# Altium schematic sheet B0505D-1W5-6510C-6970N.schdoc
size 277 x 190 mm; Device: default297x210; Symbol: default297x210; Name: default297x210; Date: 2026.03.13; Rev: V1.0; Size: "A4"; Id: /; File: B0505D-1W5-6510C-6970N; Sheet: /
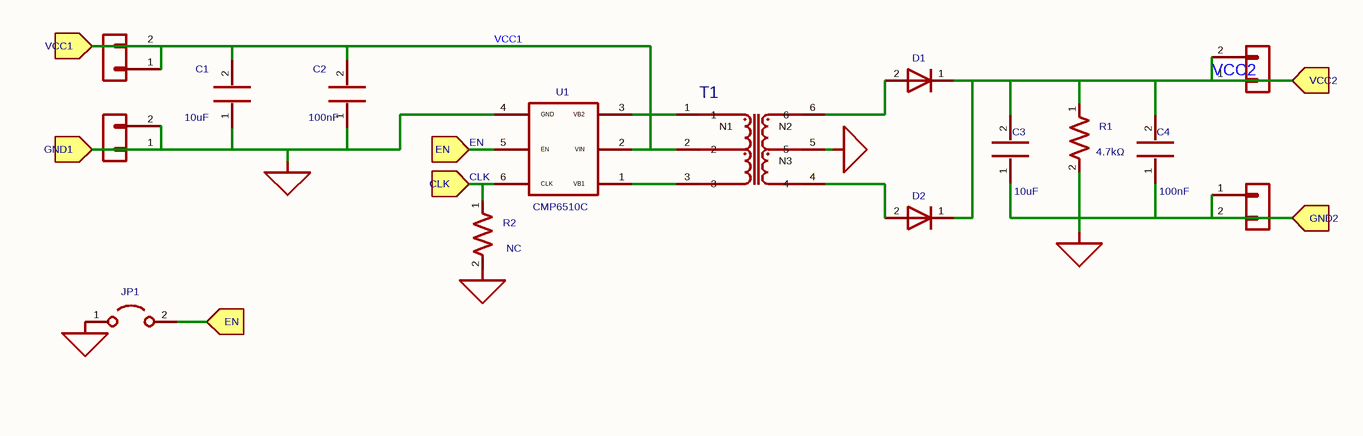
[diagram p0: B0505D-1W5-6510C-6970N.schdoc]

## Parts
C1  10uF  [MYLibrary:C0603]
C2  100nF  [MYLibrary:C0603]
C3  10uF  [MYLibrary:C0603]
C4  100nF  [MYLibrary:C0603]
D1  B5819W  [MYLibrary:SOD-123-323]  (value not drawn)
D2  B5819W  [MYLibrary:SOD-123-323]  (value not drawn)
J2  HX PZ2.54-1x2P ZZ  [Connector_PinHeader_2.54mm:PinHeader_1x02_P2.54mm_Vertical]  (value not drawn)
J3  HX PZ2.54-1x2P ZZ  [Connector_PinHeader_2.54mm:PinHeader_1x02_P2.54mm_Vertical]  (value not drawn)
J4  HX PZ2.54-1x2P ZZ  [Connector_PinHeader_2.54mm:PinHeader_1x02_P2.54mm_Vertical]  (value not drawn)
J5  Connector_Generic_Conn_01x02  [Connector_PinHeader_2.54mm:PinHeader_1x02_P2.54mm_Vertical]  (value not drawn)
JP1  Jumper_Jumper_2_Open  [Connector_PinHeader_2.54mm:PinHeader_1x02_P2.54mm_Vertical]  (value not drawn)
R1  4.7kΩ  [MYLibrary:R0603]
R2  value NC  [MYLibrary:R0603]  (hidden comment: My_Library_R)
T1  (no value)  [CMT6970N]
U1  value CMP6510C  [MYLibrary:SOT23-6]  (hidden comment: MYLibrary _CMP6510C)

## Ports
CLK (in), EN (in), GND1 (in), GND2 (in), VCC1 (in), VCC2 (in)

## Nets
GND1: C1.1 C2.1 J3.1(Pin_1) J3.2(Pin_2) JP1.1(A) R2.2 U1.4(GND) ; port GND1
GND2: C3.1 C4.1 J5.1(Pin_1) J5.2(Pin_2) R1.2 T1.5 ; port GND2
CLK: R2.1 U1.6(CLK) ; port CLK
EN: JP1.2(B) U1.5(EN) ; port EN
VCC1: C1.2 C2.2 J2.1(Pin_1) J2.2(Pin_2) T1.2 U1.2(VIN) ; port VCC1
VCC2: C3.2 C4.2 D1.1(K) D2.1(K) J4.1(Pin_1) J4.2(Pin_2) R1.1 ; port VCC2
NetD1_2: D1.2(A) T1.6
NetD2_2: D2.2(A) T1.4
NetT1_1: T1.1 U1.3(VB2)
NetT1_3: T1.3 U1.1(VB1)

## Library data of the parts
C1 = 0603X106K100NT: 容值:10uF;精度:±10%;额定电压:10V;温度系数:X5R;; Manufacturer: FH(风华); Symbol: My_Library_C; Add into BOM: yes; 3D Model: ac125912035d415993ca9572d50418b1; 3D Model Transform: 62.992,31.496,0,0,0,0,0,0,0; Tolerance: ±10%; Voltage Rating: 10V; Temperature Coefficient: X5R; ki_keywords: cap capacitor; ki_fp_filters: C_*; UniqueId: 5fb4f22ffcb6a001; ModelName: C0603_L1.6-W0.8-H0.8
C2 = CC0603KRX7R9BB104: 容值:100nF;精度:±10%;额定电压:50V;温度系数:X7R;; Manufacturer: YAGEO(国巨); Symbol: My_Library_C; Add into BOM: yes; 3D Model: ac125912035d415993ca9572d50418b1; 3D Model Transform: 62.992,31.496,0,0,0,0,0,0,0; Tolerance: ±10%; Voltage Rating: 50V; Temperature Coefficient: X7R; ki_keywords: cap capacitor; ki_fp_filters: C_*; UniqueId: 21d50210554cb61f; ModelName: C0603_L1.6-W0.8-H0.8
C3 = 0603X106K100NT: 容值:10uF;精度:±10%;额定电压:10V;温度系数:X5R;; Manufacturer: FH(风华); Symbol: My_Library_C; Add into BOM: yes; 3D Model: ac125912035d415993ca9572d50418b1; 3D Model Transform: 62.992,31.496,0,0,0,0,0,0,0; Tolerance: ±10%; Voltage Rating: 10V; Temperature Coefficient: X5R; ki_keywords: cap capacitor; ki_fp_filters: C_*; ModelName: C0603_L1.6-W0.8-H0.8
C4 = CC0603KRX7R9BB104: 容值:100nF;精度:±10%;额定电压:50V;温度系数:X7R;; Manufacturer: YAGEO(国巨); Symbol: My_Library_C; Add into BOM: yes; 3D Model: ac125912035d415993ca9572d50418b1; 3D Model Transform: 62.992,31.496,0,0,0,0,0,0,0; Tolerance: ±10%; Voltage Rating: 50V; Temperature Coefficient: X7R; ki_keywords: cap capacitor; ki_fp_filters: C_*; ModelName: C0603_L1.6-W0.8-H0.8
D1 D2 = B5819W_C7420330: 二极管配置:独立式;正向压降(Vf):600mV@1.0A;直流反向耐压(Vr):40V;整流电流:1A;; Manufacturer: R+O(宏嘉诚); Symbol: My_Library_D; Add into BOM: yes; 3D Model: 5054d9b7be8b429dad093a54b517b4dd; 3D Model Transform: 145.669,61.024,0,0,0,0,0,0,0; Diode Configuration: 独立式; Voltage - DC Reverse(Vr): 40V; Current - Rectified: 1A; Reverse Leakage Current (Ir): 1mA@30V; Operating Junction Temperature Range: -55℃~+150℃; Non-Repetitive Peak Forward Surge Current: 9A; Value: D; ki_keywords: diode; ki_fp_filters: TO-???* *_Diode_* *SingleDiode* D_*; ModelName: SOD-123_L2.7-W1.6-LS3.7-FD
J2 = HX PZ2.54-1x2P ZZ: 插针结构:1x2P;间距:2.54mm;行距:-;圆针/方针:方针;安装方式:直插;排数:单排;总PIN位数:2P;额定电流:3A;额定电压:1kV;配合针长度:6mm;塑高:2.5mm;端接针长度:3mm;触头材质:黄铜;触头镀层:金;工作温度:-40℃~+105℃;颜色:黑色;; Manufacturer: hanxia(韩下); Symbol: Connector_Generic_Conn_01x02; Add into BOM: yes; 3D Model: c7a9f3c3e6e34627af2bf939e464cb35; 3D Model Transform: 200,100,0,0,0,0,0,0,-118.11; Pin Structure: 1x2P; Pitch: 2.54mm; Circluar Pins/Square Pins: 方针; Current Rating: 3A; Voltage Rating (Max): 1kV; ki_keywords: connector; ki_fp_filters: Connector*:*_1x??_*; UniqueId: 42913bc3a3449998; ModelName: HDR-TH_2P-P2.54-M-LI-1X2P
J3 = HX PZ2.54-1x2P ZZ: 插针结构:1x2P;间距:2.54mm;行距:-;圆针/方针:方针;安装方式:直插;排数:单排;总PIN位数:2P;额定电流:3A;额定电压:1kV;配合针长度:6mm;塑高:2.5mm;端接针长度:3mm;触头材质:黄铜;触头镀层:金;工作温度:-40℃~+105℃;颜色:黑色;; Manufacturer: hanxia(韩下); Symbol: Connector_Generic_Conn_01x02; Add into BOM: yes; 3D Model: c7a9f3c3e6e34627af2bf939e464cb35; 3D Model Transform: 200,100,0,0,0,0,0,0,-118.11; Pin Structure: 1x2P; Pitch: 2.54mm; Circluar Pins/Square Pins: 方针; Current Rating: 3A; Voltage Rating (Max): 1kV; ki_keywords: connector; ki_fp_filters: Connector*:*_1x??_*; UniqueId: 6ca7fcf0d18ad80e; ModelName: HDR-TH_2P-P2.54-M-LI-1X2P
J4 = HX PZ2.54-1x2P ZZ: 插针结构:1x2P;间距:2.54mm;行距:-;圆针/方针:方针;安装方式:直插;排数:单排;总PIN位数:2P;额定电流:3A;额定电压:1kV;配合针长度:6mm;塑高:2.5mm;端接针长度:3mm;触头材质:黄铜;触头镀层:金;工作温度:-40℃~+105℃;颜色:黑色;; Manufacturer: hanxia(韩下); Symbol: Connector_Generic_Conn_01x02; Add into BOM: yes; 3D Model: c7a9f3c3e6e34627af2bf939e464cb35; 3D Model Transform: 200,100,0,0,0,0,0,0,-118.11; Pin Structure: 1x2P; Pitch: 2.54mm; Circluar Pins/Square Pins: 方针; Current Rating: 3A; Voltage Rating (Max): 1kV; ki_keywords: connector; ki_fp_filters: Connector*:*_1x??_*; ModelName: HDR-TH_2P-P2.54-M-LI-1X2P
J5 = Connector_Generic_Conn_01x02: ki_fp_filters: Jumper* TestPoint*2Pads* TestPoint*Bridge*; Attribute1: JP1; AddInBom: yes
JP1 = Jumper_Jumper_2_Open: Jumper, 2-pole, open; ki_keywords: Jumper SPST; ki_fp_filters: Jumper* TestPoint*2Pads* TestPoint*Bridge*; Attribute1: JP1; AddInBom: yes
R1 = RC0603FR-074K7L: 电阻类型:厚膜电阻;阻值:4.7kΩ;精度:±1%;功率:100mW;工作电压:75V;温度系数:±100ppm/℃;; Manufacturer: YAGEO(国巨); Symbol: My_Library_R; Add into BOM: yes; 3D Model: fc143cca1e79419f9cd78b61e9279f08; 3D Model Transform: 31.8897,63.7794,0,90,0,0,0,0,0; Tolerance: ±1%; Power(Watts): 100mW; Voltage-Supply(Max): 75V; ki_keywords: R res resistor; ki_fp_filters: R_*; ModelName: R0603
R2 = My_Library_R: Add into BOM: no; ki_keywords: R res resistor; ki_fp_filters: R_*; UniqueId: 06442d24ab060343; Attribute1: R2
T1 = CMT6970N: AddInBom: yes
U1 = MYLibrary _CMP6510C: UniqueId: 48a4a086d8c42a18; Attribute1: U1; AddInBom: yes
